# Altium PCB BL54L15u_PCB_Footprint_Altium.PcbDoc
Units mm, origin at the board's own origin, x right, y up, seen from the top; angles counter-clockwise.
Board outline 7.9 x 6.3 mm, 2 copper layers (Top Layer, Bottom Layer); 1 components, 0 nets, 51 pads, 0 vias.
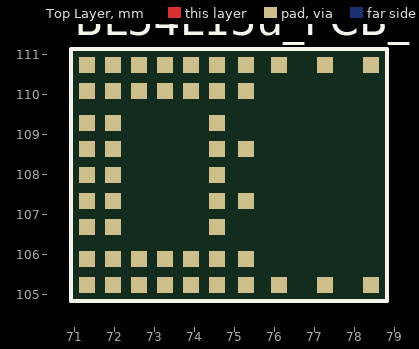
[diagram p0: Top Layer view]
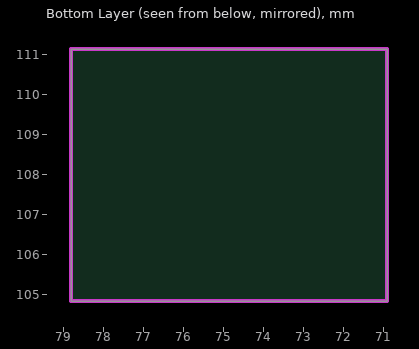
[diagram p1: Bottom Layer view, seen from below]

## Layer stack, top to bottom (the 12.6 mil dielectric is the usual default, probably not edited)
Top Solder: solder mask 0.0102, Solder Resist, Dk 3.5
Top Layer: signal copper 0.0356
Dielectric 1: dielectric 0.32, FR-4, Dk 4.8
Bottom Layer: signal copper 0.0356
Bottom Solder: solder mask 0.0102, Solder Resist, Dk 3.5

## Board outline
70.923,104.84 78.823,104.84 78.823,111.14 70.923,111.14

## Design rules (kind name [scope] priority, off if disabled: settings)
Clearance [All] p1: gap=0.254 ignorepadtopadclearanceinfootprint=FALSE
PolygonConnect [All] p1: connectstyle=Relief reliefconductorwidth=0.254 reliefentries=4 polygonreliefangle="90 Angle" airgapwidth=0.254
RoutingVias [All] p1: holewidth=0.711 width=1.27 viastyle="Through Hole" minholewidth=0.711 minwidth=1.27 maxholewidth=0.711 maxwidth=1.27
SolderMaskExpansion [All] p1: expansion=0.102 istentingtop=FALSE
Width [All] p1: maxlimit=0.254 minlimit=0.102 preferedwidth=0.254
30 further rules are at their usual default settings.

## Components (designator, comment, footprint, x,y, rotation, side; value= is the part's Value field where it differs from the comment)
BL54L15u_PCB_Footprint_Altium "Comment" "Ezurio, BL54L15u Module, Platform Side" 70.923,104.84 r0 top

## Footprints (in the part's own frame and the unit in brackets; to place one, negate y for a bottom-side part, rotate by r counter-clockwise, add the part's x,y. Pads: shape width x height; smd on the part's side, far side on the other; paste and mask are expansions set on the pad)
"Ezurio, BL54L15u Module, Platform Side" [mm] "Ezurio, BL54L15u Module, Platform Side"
  rect 0.4x0.4 smd paste+0 mask+0.051: 1(0.4,5.9) 2(1.05,5.9) 3(0.4,5.25) 4(1.05,5.25) 5(0.4,4.45) 6(1.05,4.45) 7(0.4,3.8) 8(1.05,3.8) 9(0.4,3.15) 10(1.05,3.15) 11(0.4,2.5) 12(1.05,2.5) 13(0.4,1.85) 14(1.05,1.85) 15(0.4,1.05) 16(1.05,1.05) 17(0.4,0.4) 18(1.05,0.4) 19(1.7,0.4) 20(1.7,1.05) 21(2.35,0.4) 22(2.35,1.05) 23(3,0.4) 24(3,1.05) 25(3.65,0.4) 26(3.65,1.05) 27(4.375,0.4) 28(4.375,1.05) 29(3.65,1.85) 30(3.65,2.5) 31(4.375,2.5) 32(3.65,3.15) 33(3.65,3.8) 34(4.375,3.8) 35(3.65,4.45) 36(4.375,5.25) 37(4.375,5.9) 38(3.65,5.25) 39(3.65,5.9) 40(3,5.25) 41(3,5.9) 42(2.35,5.25) 43(2.35,5.9) 44(1.7,5.25) 45(1.7,5.9) G1(5.2,5.9) G2(6.35,5.9) G3(7.5,5.9) G4(5.2,0.4) G5(6.35,0.4) G6(7.5,0.4)
  Top Layer pour cut-out: 4.9,5.65 4.9,5.65 4.9,0.65 7.9,0.65 7.9,5.65
  silkscreen extent 0,0 7.9,6.3, body extent 0.2,0.2 7.7,6.1, height 0.01

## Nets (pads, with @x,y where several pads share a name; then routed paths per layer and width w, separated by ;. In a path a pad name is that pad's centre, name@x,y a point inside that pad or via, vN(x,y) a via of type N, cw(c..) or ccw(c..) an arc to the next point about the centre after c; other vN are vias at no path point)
pads on no net: BL54L15u_PCB_Footprint_Altium.1 BL54L15u_PCB_Footprint_Altium.2 BL54L15u_PCB_Footprint_Altium.3 BL54L15u_PCB_Footprint_Altium.4 BL54L15u_PCB_Footprint_Altium.5 BL54L15u_PCB_Footprint_Altium.6 BL54L15u_PCB_Footprint_Altium.7 BL54L15u_PCB_Footprint_Altium.8 BL54L15u_PCB_Footprint_Altium.9 BL54L15u_PCB_Footprint_Altium.10 BL54L15u_PCB_Footprint_Altium.11 BL54L15u_PCB_Footprint_Altium.12 BL54L15u_PCB_Footprint_Altium.13 BL54L15u_PCB_Footprint_Altium.14 BL54L15u_PCB_Footprint_Altium.15 BL54L15u_PCB_Footprint_Altium.16 BL54L15u_PCB_Footprint_Altium.17 BL54L15u_PCB_Footprint_Altium.18 BL54L15u_PCB_Footprint_Altium.19 BL54L15u_PCB_Footprint_Altium.20 BL54L15u_PCB_Footprint_Altium.21 BL54L15u_PCB_Footprint_Altium.22 BL54L15u_PCB_Footprint_Altium.23 BL54L15u_PCB_Footprint_Altium.24 BL54L15u_PCB_Footprint_Altium.25 BL54L15u_PCB_Footprint_Altium.26 BL54L15u_PCB_Footprint_Altium.27 BL54L15u_PCB_Footprint_Altium.28 BL54L15u_PCB_Footprint_Altium.29 BL54L15u_PCB_Footprint_Altium.30 BL54L15u_PCB_Footprint_Altium.31 BL54L15u_PCB_Footprint_Altium.32 BL54L15u_PCB_Footprint_Altium.33 BL54L15u_PCB_Footprint_Altium.34 BL54L15u_PCB_Footprint_Altium.35 BL54L15u_PCB_Footprint_Altium.36 BL54L15u_PCB_Footprint_Altium.37 BL54L15u_PCB_Footprint_Altium.38 BL54L15u_PCB_Footprint_Altium.39 BL54L15u_PCB_Footprint_Altium.40 BL54L15u_PCB_Footprint_Altium.41 BL54L15u_PCB_Footprint_Altium.42 BL54L15u_PCB_Footprint_Altium.43 BL54L15u_PCB_Footprint_Altium.44 BL54L15u_PCB_Footprint_Altium.45 BL54L15u_PCB_Footprint_Altium.G1 BL54L15u_PCB_Footprint_Altium.G2 BL54L15u_PCB_Footprint_Altium.G3 BL54L15u_PCB_Footprint_Altium.G4 BL54L15u_PCB_Footprint_Altium.G5 BL54L15u_PCB_Footprint_Altium.G6

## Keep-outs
Keep-Out Layer:
  the board outline again, w0.102

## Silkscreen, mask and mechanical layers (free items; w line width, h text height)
Mechanical 1:
  lines w0.025: 75.823,105.49 75.823,110.49 78.823,110.49 78.823,105.49 75.823,105.49
  lines w0.102: 70.923,104.84 78.823,104.84 78.823,111.14 70.923,111.14 70.923,104.84
  text "Keep Out Area" at 77.104,109.92 h0.38 r270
